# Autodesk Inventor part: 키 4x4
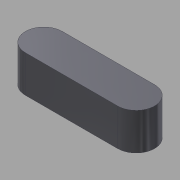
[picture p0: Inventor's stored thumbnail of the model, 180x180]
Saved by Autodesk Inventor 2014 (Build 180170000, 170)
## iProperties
Created: 2014-10
Part Number: 키 4x4
Document SubType Name: Modeling
Designer: KYOUNG IL JANG
Density: 7.86 g/cm^3
Mass: 1.65269 g
Surface Area: 2.35398 cm^2
Volume: 0.210265 cm^3
Material: 강철, 연강
Appearance: 강철 - 광택
Author: SeoGD™ [www.esajin.kr]
Revision Number: 1
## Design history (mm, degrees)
sketch "스케치1"
  geometry: L1 (-5, -2)-(5, -2); L2 (5, 2)-(-5, 2); A1 r 2 centre (5, 0) between (5, -2) and (5, 2); A2 r 2 centre (-5, 0) between (-5, 2) and (-5, -2); 2 further points
  constraints: 4 end point, 4 point on circle, 4 tangent, 2 centre point, 1 horizontal, 1 horizontal alignment, 1 midpoint, 1 parallel, 1 vertical alignment
  dimensions: "d0" = 4 distance between parallel lines of L1 L2; "d1" = 14 dimension on A1 A2
extrude "돌출1" new body sketch "스케치1" stored distance "d2" = 4; taper "d3" = 0 deg
node "솔리드1"
